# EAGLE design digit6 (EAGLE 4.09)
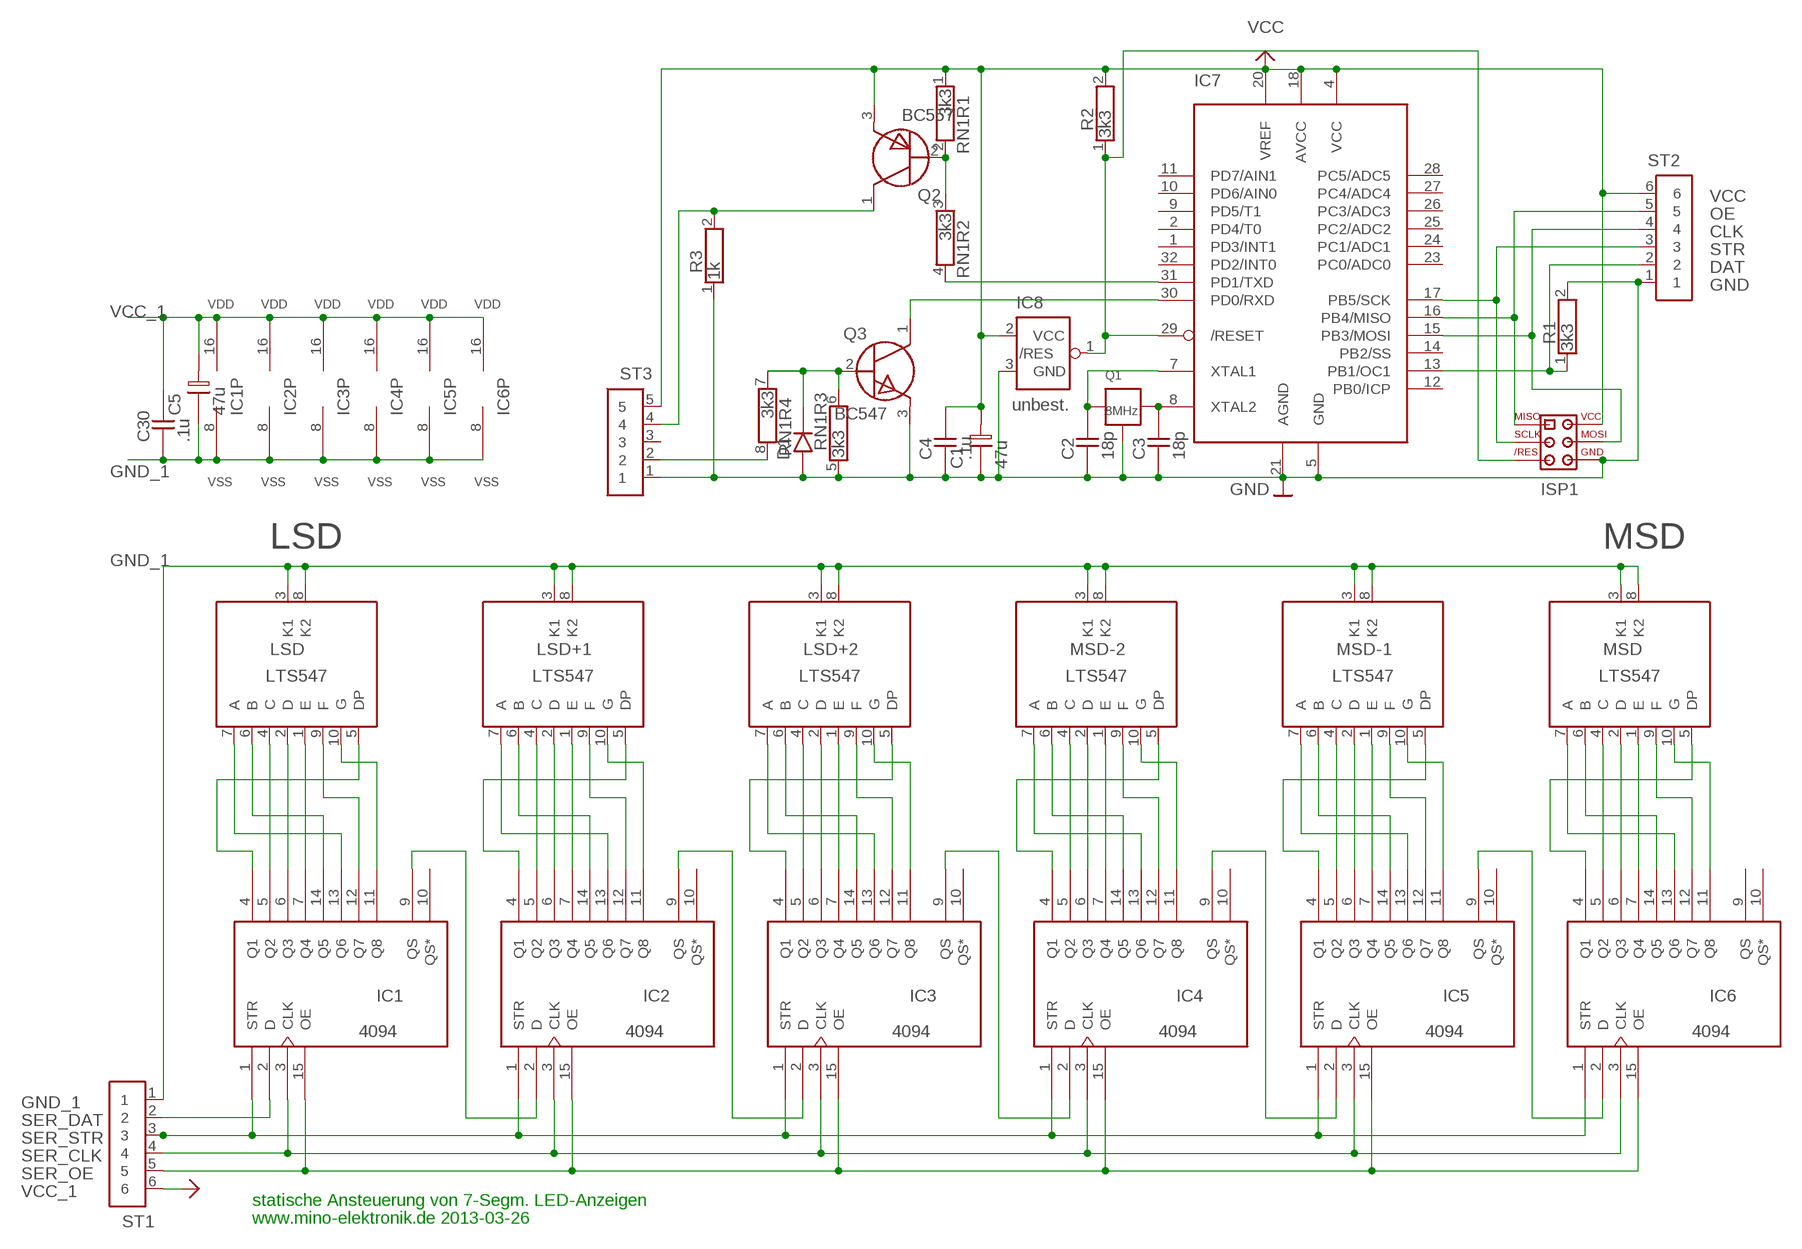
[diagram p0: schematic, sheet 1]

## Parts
C1  47u  ELK01  [02P100RA]
C2  18p  CAP01  [02P100QA]
C3  18p  CAP01  [02P100QA]
C4  .1u  CAP01  [02P100QA]
C5  47u  ELK01  [02P100RA]
C30  .1u  CAP01  [02P100QA]
D1  DIO03  [02P300IV]
IC1  4094  [SO-16]
IC2  4094  [SO-16]
IC3  4094  [SO-16]
IC4  4094  [SO-16]
IC5  4094  [SO-16]
IC6  4094  [SO-16]
IC7  90S4433F  [TQFP-32]
IC8  unbest.  MC34164  [TO92]
ISP1  AVR_ISP  [CON03X2]
LSD  LTS547  [SEGM13MM]
LSD+1  LTS547  [SEGM13MM]
LSD+2  LTS547  [SEGM13MM]
MSD  LTS547  [SEGM13MM]
MSD-1  LTS547  [SEGM13MM]
MSD-2  LTS547  [SEGM13MM]
Q1  8MHz  KERAM_RES  [KERAMRES]
Q2  BC557  BC327  [TO92]
Q3  BC547  BC337  [TO92]
R1  3k3  RES04  [02P400IL]
R2  3k3  RES04  [02P400IL]
R3  1k  RES04  [02P400IL]
RN1  3k3  R4P8  [08P100QA]
ST1  ST_6X1  [6X1]
ST2  ST_6X1  [6X1]
ST3  ST_5X1  [5X1]

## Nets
CLK: IC7.15(PB3/MOSI) ISP1.4 ST2.4
DAT: IC7.13(PB1/OC1) R1.1 ST2.2
GND: C1.N C2.1 C3.1 C4.1 D1.A IC7.5(GND) IC7.21(AGND) IC8.3(GND) ISP1.6 Q1.3 Q3.3(E) R1.2 R3.1 RN1.5 ST2.1 ST3.1
GND_1: C5.N C30.1 IC1.8(VSS) IC2.8(VSS) IC3.8(VSS) IC4.8(VSS) IC5.8(VSS) IC6.8(VSS) LSD+1.3(K1) LSD+1.8(K2) LSD+2.3(K1) LSD+2.8(K2) LSD.3(K1) LSD.8(K2) MSD-1.3(K1) MSD-1.8(K2) MSD-2.3(K1) MSD-2.8(K2) MSD.3(K1) MSD.8(K2) ST1.1
N$1: C3.2 IC7.8(XTAL2) Q1.2
N$2: C2.2 IC7.7(XTAL1) Q1.1
N$3: Q2.2(B) RN1.2 RN1.3
N$4: D1.K Q3.2(B) RN1.6 RN1.7
N$5: IC7.30(PD0/RXD) Q3.1(C)
N$6: IC7.29(/RESET) IC8.1(/RES) ISP1.5 R2.1
N$7: IC7.31(PD1/TXD) RN1.4
N$34: IC1.13(Q6) LSD.7(A)
N$35: IC1.14(Q5) LSD.6(B)
N$36: IC1.5(Q2) LSD.4(C)
N$37: IC1.6(Q3) LSD.2(D)
N$38: IC1.7(Q4) LSD.1(E)
N$39: IC1.12(Q7) LSD.9(F)
N$40: IC1.11(Q8) LSD.10(G)
N$41: IC1.4(Q1) LSD.5(DP)
N$42: IC2.13(Q6) LSD+1.7(A)
N$43: IC2.14(Q5) LSD+1.6(B)
N$44: IC2.5(Q2) LSD+1.4(C)
N$45: IC2.6(Q3) LSD+1.2(D)
N$46: IC2.7(Q4) LSD+1.1(E)
N$47: IC2.12(Q7) LSD+1.9(F)
N$48: IC2.11(Q8) LSD+1.10(G)
N$49: IC2.4(Q1) LSD+1.5(DP)
N$50: IC3.13(Q6) LSD+2.7(A)
N$51: IC3.14(Q5) LSD+2.6(B)
N$61: IC3.5(Q2) LSD+2.4(C)
N$63: IC3.6(Q3) LSD+2.2(D)
N$64: IC3.7(Q4) LSD+2.1(E)
N$65: IC3.12(Q7) LSD+2.9(F)
N$67: IC3.11(Q8) LSD+2.10(G)
N$68: IC3.4(Q1) LSD+2.5(DP)
N$69: IC4.13(Q6) MSD-2.7(A)
N$70: IC4.14(Q5) MSD-2.6(B)
N$71: IC4.5(Q2) MSD-2.4(C)
N$73: IC4.6(Q3) MSD-2.2(D)
N$74: IC4.7(Q4) MSD-2.1(E)
N$75: IC4.12(Q7) MSD-2.9(F)
N$76: IC4.11(Q8) MSD-2.10(G)
N$77: IC4.4(Q1) MSD-2.5(DP)
N$78: IC5.13(Q6) MSD-1.7(A)
N$79: IC5.14(Q5) MSD-1.6(B)
N$80: IC5.5(Q2) MSD-1.4(C)
N$81: IC5.6(Q3) MSD-1.2(D)
N$82: IC5.7(Q4) MSD-1.1(E)
N$83: IC5.12(Q7) MSD-1.9(F)
N$84: IC5.11(Q8) MSD-1.10(G)
N$85: IC5.4(Q1) MSD-1.5(DP)
N$87: IC6.13(Q6) MSD.7(A)
N$89: IC6.14(Q5) MSD.6(B)
N$90: IC6.5(Q2) MSD.4(C)
N$91: IC6.6(Q3) MSD.2(D)
N$92: IC6.7(Q4) MSD.1(E)
N$93: IC6.12(Q7) MSD.9(F)
N$94: IC6.11(Q8) MSD.10(G)
N$95: IC6.4(Q1) MSD.5(DP)
N$102: IC1.9(QS) IC2.2(D)
N$103: IC2.9(QS) IC3.2(D)
N$104: IC3.9(QS) IC4.2(D)
N$105: IC4.9(QS) IC5.2(D)
N$106: IC5.9(QS) IC6.2(D)
OE: IC7.16(PB4/MISO) ISP1.1 ST2.5
RXD: RN1.8 ST3.2
SER_CLK: IC1.3(CLK) IC2.3(CLK) IC3.3(CLK) IC4.3(CLK) IC5.3(CLK) IC6.3(CLK) ST1.4
SER_DAT: IC1.2(D) ST1.2
SER_OE: IC1.15(OE) IC2.15(OE) IC3.15(OE) IC4.15(OE) IC5.15(OE) IC6.15(OE) ST1.5
SER_STR: IC1.1(STR) IC2.1(STR) IC3.1(STR) IC4.1(STR) IC5.1(STR) IC6.1(STR) ST1.3
STR: IC7.17(PB5/SCK) ISP1.3 ST2.3
TXD: Q2.1(C) R3.2 ST3.4
VCC: C1.P C4.2 IC7.4(VCC) IC7.18(AVCC) IC7.20(VREF) IC8.2(VCC) ISP1.2 Q2.3(E) R2.2 RN1.1 ST2.6 ST3.5
VCC_1: C5.P C30.2 IC1.16(VDD) IC2.16(VDD) IC3.16(VDD) IC4.16(VDD) IC5.16(VDD) IC6.16(VDD) ST1.6
Unconnected: IC1.10(QS*) IC2.10(QS*) IC3.10(QS*) IC4.10(QS*) IC5.10(QS*) IC6.9(QS) IC6.10(QS*) IC7.1(PD3/INT1) IC7.2(PD4/T0) IC7.9(PD5/T1) IC7.10(PD6/AIN0) IC7.11(PD7/AIN1) IC7.12(PB0/ICP) IC7.14(PB2/SS) IC7.23(PC0/ADC0) IC7.24(PC1/ADC1) IC7.25(PC2/ADC2) IC7.26(PC3/ADC3) IC7.27(PC4/ADC4) IC7.28(PC5/ADC5) IC7.32(PD2/INT0) ST3.3

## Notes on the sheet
- LSD | MSD
- statische Ansteuerung von 7-Segm. LED-Anzeigen
- www.mino-elektronik.de 2013-03-26

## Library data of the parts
C1 C5 = DISCRETE:ELK01
C2-C4 C30 = DISCRETE:CAP01
D1 = DISCRETE:DIO03
IC1-IC6 = SMD_40XX:4094
IC7 = MINO:90S4433F
IC8 = MINO:MC34164
ISP1 = CONNEC:AVR_ISP
LSD LSD+1 LSD+2 MSD MSD-1 MSD-2 = MINO:LTS547
Q1 = MINO:KERAM_RES
Q2 = ANALOG:BC327
Q3 = ANALOG:BC337
R1-R3 = DISCRETE:RES04
RN1 = DISCRETE:R4P8
ST1 ST2 = CONNEC:ST_6X1
ST3 = CONNEC:ST_5X1

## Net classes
0 default: width 0.203 mm, clearance 0.406 mm

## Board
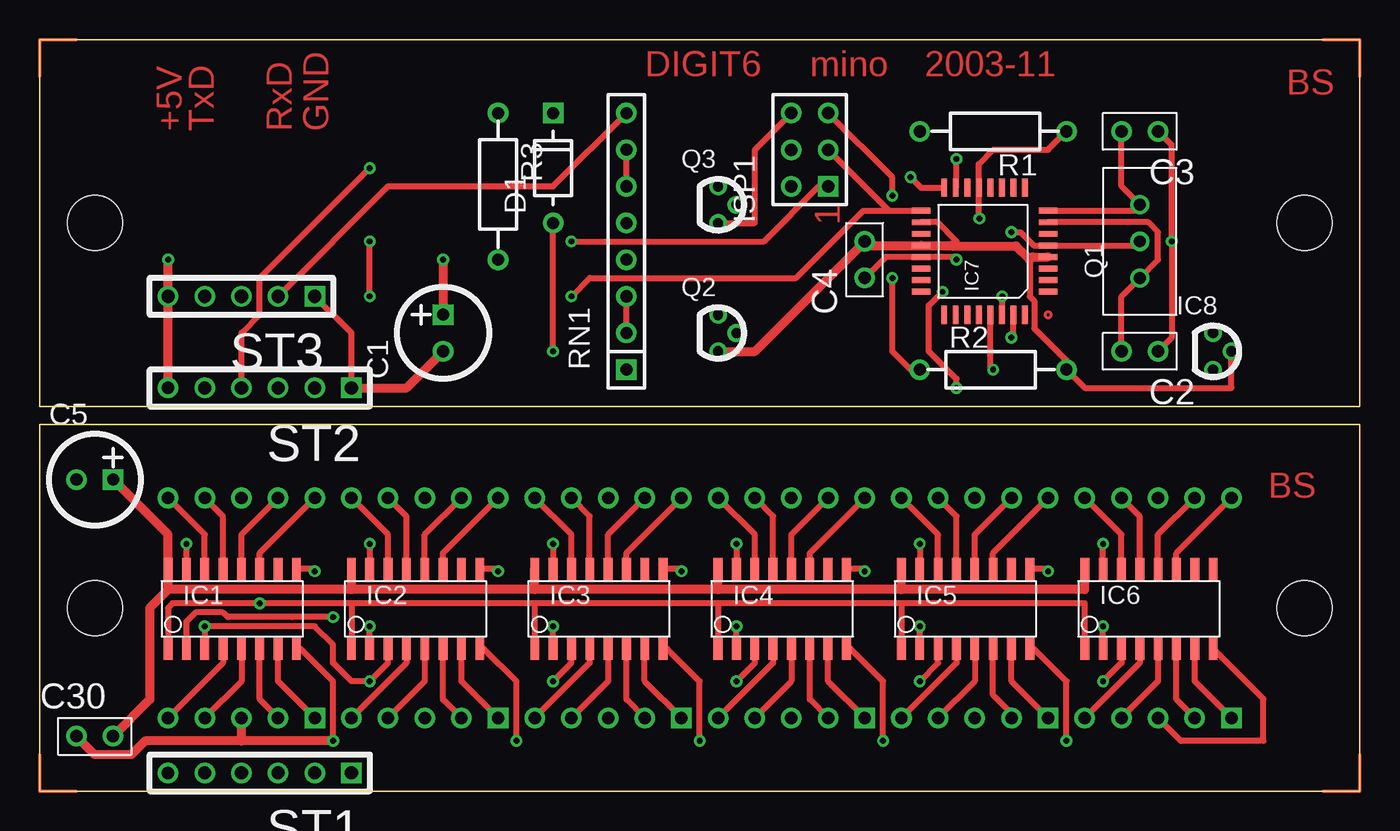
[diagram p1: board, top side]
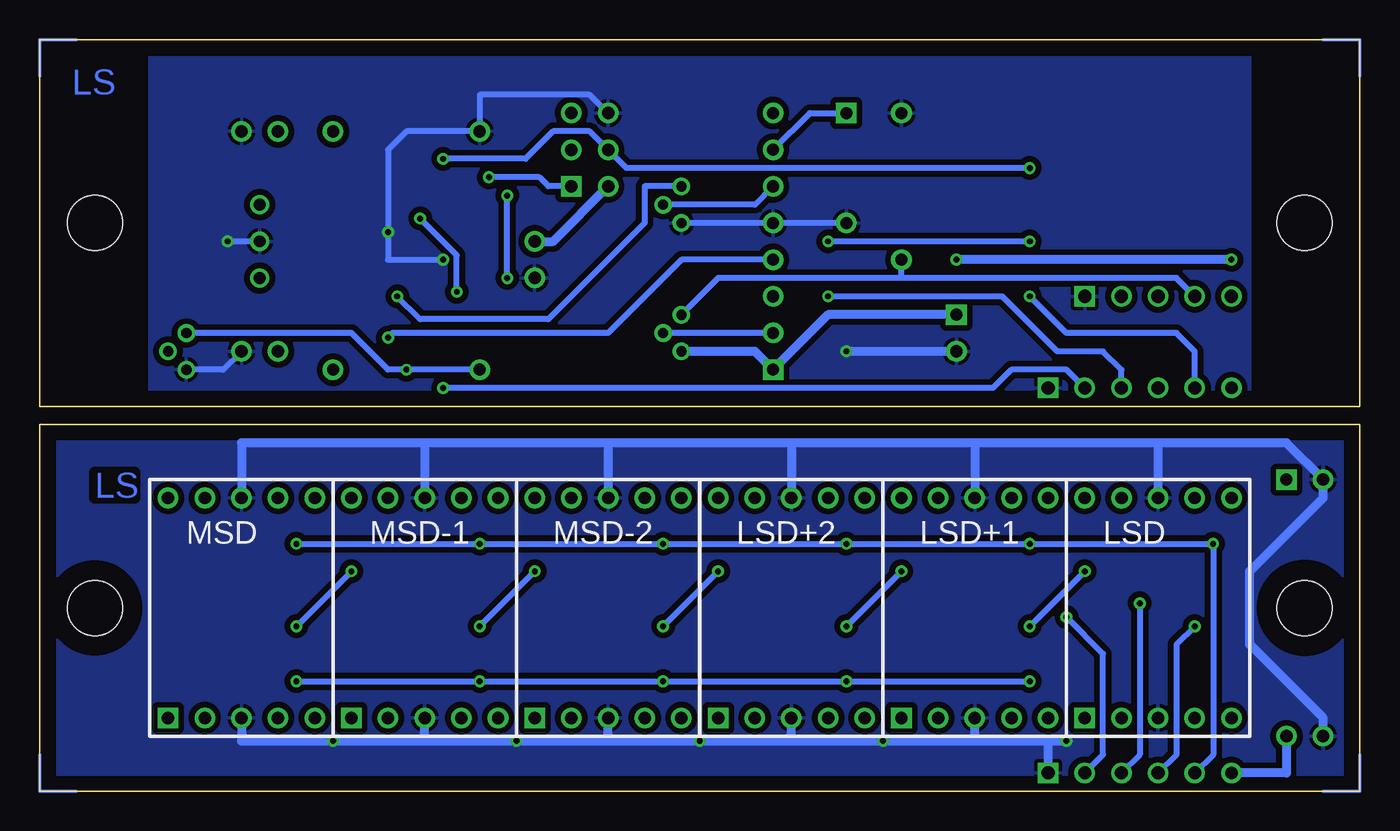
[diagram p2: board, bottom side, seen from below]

Size 91.44 x 52.07 mm. Coordinates in mm from the lower left corner, seen from the top.
Outline: 91.44,0 0,0 0,25.4 91.44,25.4 91.44,0
Outline: 0,26.67 91.44,26.67 91.44,52.07 0,52.07 0,26.67
Copper layers used: Top, Bottom
Holes 3.81 mm at 87.63,12.7 3.81,12.7 87.63,39.37 3.81,39.37
bRestrict: area 84.5,9.5 to 90.8,15.9; area 0.6,9.5 to 7,15.9

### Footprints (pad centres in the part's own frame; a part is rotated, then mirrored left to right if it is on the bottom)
02P100RA = drill 0.838 pad 1.422 round: N 0,0 | drill 0.838 pad 1.422 square: P 2.54,0
02P100QA = drill 0.864 pad 1.422 round: 1 0,0; 2 2.54,0
02P300IV = drill 0.838 pad 1.422 round: A 0,0 | drill 0.838 pad 1.422 square: K 7.62,0
SO-16 = smd 0.61 x 1.524: 1 -3.81,-2.819; 2 -2.54,-2.819; 3 -1.27,-2.819; 4 0,-2.819; 5 1.27,-2.819; 6 2.54,-2.819; 7 3.81,-2.819; 8 5.08,-2.819; 9 5.08,2.692; 10 3.81,2.692; 11 2.54,2.692; 12 1.27,2.692; 13 0,2.692; 14 -1.27,2.692; 15 -2.54,2.692; 16 -3.81,2.692
TQFP-32 = smd 0.406 x 1.27: 1 1.6,0; 2 2.4,0; 3 3.2,0; 4 4,0; 5 4.8,0; 6 5.6,0; 7 6.4,0; 8 7.2,0; 17 7.2,8.8; 18 6.4,8.8; 19 5.6,8.8; 20 4.8,8.8; 21 4,8.8; 22 3.2,8.8; 23 2.4,8.8; 24 1.6,8.8 | smd 1.27 x 0.406: 9 8.8,1.6; 10 8.8,2.4; 11 8.8,3.2; 12 8.8,4; 13 8.8,4.8; 14 8.8,5.6; 15 8.8,6.4; 16 8.8,7.2; 25 0,7.2; 26 0,6.4; 27 0,5.6; 28 0,4.8; 29 0,4; 30 0,3.2; 31 0,2.4; 32 0,1.6
TO92 = drill 0.711 pad 1.118 round: 1 0,2.54; 2 1.27,1.27; 3 0,0
CON03X2 = drill 0.864 pad 1.422 square: 1 0,0 | drill 0.864 pad 1.422 round: 2 0,2.54; 3 2.54,0; 4 2.54,2.54; 5 5.08,0; 6 5.08,2.54
SEGM13MM = drill 0.864 pad 1.422 square: 1 0,0 | drill 0.864 pad 1.422 round: 2 2.54,0; 3 5.08,0; 4 7.62,0; 5 10.16,0; 6 10.16,15.24; 7 7.62,15.24; 8 5.08,15.24; 9 2.54,15.24; 10 0,15.24
KERAMRES = drill 0.813 round: 1 -2.54,0; 2 2.54,0; 3 0,0
02P400IL = drill 0.838 pad 1.422 round: 1 0,0; 2 10.16,0
08P100QA = drill 0.838 pad 1.422 square: 1 0,0 | drill 0.838 pad 1.422 round: 2 2.54,0; 3 5.08,0; 4 7.62,0; 5 10.16,0; 6 12.7,0; 7 15.24,0; 8 17.78,0
6X1 = drill 0.914 pad 1.422 square: 1 1.27,1.27 | drill 0.914 pad 1.422 round: 2 3.81,1.27; 3 6.35,1.27; 4 8.89,1.27; 5 11.43,1.27 | drill 0.864 pad 1.422 round: 6 13.97,1.27
5X1 = drill 0.914 pad 1.422 square: 1 0,0 | drill 0.914 pad 1.422 round: 2 2.54,0; 3 5.08,0; 4 7.62,0; 5 10.16,0

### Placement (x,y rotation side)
C1  27.94,30.48 90 top
C2  77.47,30.48 180 top
C3  77.47,45.72 180 top
C4  57.15,35.56 90 top
C5  2.54,21.59 0 top
C30  2.54,3.81 0 top
D1  35.56,39.37 90 top
IC1  12.7,12.7 0 top
IC2  25.4,12.7 0 top
IC3  38.1,12.7 0 top
IC4  50.8,12.7 0 top
IC5  63.5,12.7 0 top
IC6  76.2,12.7 0 top
IC7  69.85,33.02 90 top
IC8  81.28,29.21 0 top
ISP1  54.61,41.91 90 top
LSD  19.05,5.08 0 bottom
LSD+1  31.75,5.08 0 bottom
LSD+2  44.45,5.08 0 bottom
MSD  82.55,5.08 0 bottom
MSD-1  69.85,5.08 0 bottom
MSD-2  57.15,5.08 0 bottom
Q1  76.2,38.1 90 top
Q2  46.99,30.48 0 top
Q3  46.99,39.37 0 top
R1  71.12,45.72 180 top
R2  60.96,29.21 0 top
R3  31.75,46.99 270 top
RN1  40.64,29.21 90 top
ST1  22.86,2.54 180 top
ST2  22.86,29.21 180 top
ST3  19.05,34.29 180 top

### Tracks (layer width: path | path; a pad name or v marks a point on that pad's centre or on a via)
CLK  (via drill 0.41)
  Top 0.406: IC7.15 63.45,43.77 v63.5,43.81 | v22.86,43.18 15.24,35.56 15.24,33.02 13.97,31.75 ST2.4
  Bottom 0.406: v63.5,43.81 57.78,43.81 55.88,45.72 53.34,45.72 ISP1.4 50.8,43.18 v22.86,43.18
DAT  (via drill 0.41)
  Top 0.406: R1.1 69.85,44.45 66.04,44.45 65.05,43.46 IC7.13 65.05,39.73 v65.09,39.69 | v62.55,34.61 61.59,33.66 61.59,30.48 63.5,28.57 v63.5,27.94
  Bottom 0.406: v65.09,39.69 62.55,37.15 v62.55,34.61 | v63.5,27.94 25.4,27.94 24.13,29.21 20.32,29.21 ST2.2
GND  (via drill 0.41)
  Top 0.406: ST2.1 21.59,31.75 ST3.1 | v35.56,30.48 D1.A | C4.1 58.61,37.02 IC7.21 63.31,37.02 v63.5,36.83 | v67.31,38.73 67.94,38.73 68.86,37.82 IC7.5 75.92,37.82 Q1.3 | C3.1 78.42,44.77 v78.42,38.1 78.42,31.43 C2.1 | ISP1.6 49.53,44.45 49.53,39.37 Q3.3
  Top 0.61: ST2.1 25.4,27.94 C1.N
  Bottom 0.406: D1.A RN1.5 Q3.3 | v63.5,36.83 67.31,36.83 v67.31,38.73 67.31,44.45 66.04,45.72 R1.2 60.96,48.26 53.34,48.26 ISP1.6 | Q1.3 v78.42,38.1 | IC8.3 78.74,29.21 C2.1
  Bottom 0.61: C1.N v35.56,30.48
  pour Bottom: 7.62,51.44 7.62,27.3 83.82,27.62 83.82,51.44
GND_1  (via drill 0.41)
  Top 0.406: IC6.8 84.77,6.39 84.77,3.49 79.06,3.49 MSD.3 | IC5.8 68.86,9.88 71.12,7.62 v71.12,3.49 | IC4.8 56.16,9.88 58.42,7.62 v58.42,3.49 | IC3.8 43.46,9.88 45.72,7.62 v45.72,3.49 | IC2.8 30.76,9.88 33.02,7.62 v33.02,3.49 | IC1.8 18.06,9.88 20.32,7.62 v20.32,3.49
  Top 0.61: 13.97,3.49 LSD.3 | v20.32,3.49 13.97,3.49 | 13.97,3.49 7.3,3.49 6.35,2.54 3.81,2.54 C30.1
  Bottom 0.61: 26.67,3.49 v20.32,3.49 | 26.67,3.49 LSD+1.3 | 21.59,3.49 ST1.1 | 39.37,3.49 v33.02,3.49 26.67,3.49 | 52.07,3.49 v45.72,3.49 39.37,3.49 | 64.77,3.49 v58.42,3.49 52.07,3.49 | 64.77,3.49 v71.12,3.49 77.47,3.49 MSD.3 | 64.77,3.49 MSD-1.3 | 52.07,3.49 MSD-2.3 | 39.37,3.49 LSD+2.3 | C30.1 2.54,5.08 7.62,10.16 7.62,15.24 2.54,20.32 C5.N 5.08,24.13 13.97,24.13 | 13.97,24.13 LSD.8 | 13.97,24.13 26.67,24.13 | 26.67,24.13 39.37,24.13 | 39.37,24.13 52.07,24.13 | 52.07,24.13 64.77,24.13 | 64.77,24.13 77.47,24.13 MSD.8 | 64.77,24.13 MSD-1.8 | 52.07,24.13 MSD-2.8 | 39.37,24.13 LSD+2.8 | 26.67,24.13 LSD+1.8
  pour Bottom: 90.81,24.77 90.81,0.64 0.64,0.64 0.64,24.77
N$1
  Top 0.406: IC7.8 75.78,40.22 Q1.2 74.93,41.91 C3.2
N$2
  Top 0.406: IC7.7 76.78,39.42 77.47,38.73 77.47,36.83 Q1.1 74.93,34.29 C2.2
N$3
  Top 0.406: RN1.2 RN1.3
  Bottom 0.406: RN1.2 Q2.2
N$4
  Top 0.406: RN1.6 RN1.7
  Bottom 0.406: D1.K 38.1,46.99 RN1.7 | Q3.2 41.91,40.64 RN1.6
N$5  (via drill 0.41)
  Top 0.406: IC7.30 66.65,34.27 v66.67,34.29
  Bottom 0.406: v66.67,34.29 65.09,32.7 56.2,32.7 49.53,39.37 49.53,41.91 Q3.1
N$6  (via drill 0.41)
  Top 0.406: IC7.29 65.85,29.4 v66.04,29.21 | R2.1 60.33,29.21 59.05,30.48 v59.05,35.56 | v59.05,41.27 59.05,42.55 ISP1.5
  Bottom 0.406: IC8.1 69.85,31.75 67.31,29.21 v66.04,29.21 R2.1 | v59.05,35.56 v59.05,41.27
N$7  (via drill 0.41)
  Top 0.406: IC7.31 67.45,31.57 v67.31,31.43
  Bottom 0.406: RN1.4 46.99,36.83 52.07,31.75 66.99,31.75 v67.31,31.43
N$8
  Bottom 0.254: 88.9,52.07 91.44,52.07 91.44,49.53
N$9
  Top 0.254: 88.9,52.07 91.44,52.07 91.44,49.53
N$10
  Bottom 0.254: 2.54,0 0,0 0,2.54
N$13
  Top 0.254: 2.54,0 0,0 0,2.54
N$14
  Top 0.254: 91.44,2.54 91.44,0 88.9,0
N$15
  Bottom 0.254: 88.9,0 91.44,0 91.44,2.54
N$16
  Top 0.254: 2.54,52.07 0,52.07 0,49.53
N$17
  Bottom 0.254: 2.54,52.07 0,52.07 0,49.53
N$34
  Top 0.406: IC1.13 12.7,19.05 LSD.7
N$35
  Top 0.406: IC1.14 11.43,17.78 LSD.6
N$36
  Top 0.406: IC1.5 13.97,7.62 LSD.4
N$37
  Top 0.406: IC1.6 15.24,6.35 LSD.2
N$38
  Top 0.406: IC1.7 16.51,7.62 LSD.1
N$39
  Top 0.406: IC1.12 13.97,17.78 LSD.9
N$40
  Top 0.406: IC1.11 15.24,16.51 LSD.10
N$41
  Top 0.406: IC1.4 12.7,8.89 LSD.5
N$42
  Top 0.406: IC2.13 25.4,19.05 LSD+1.7
N$43
  Top 0.406: IC2.14 24.13,17.78 LSD+1.6
N$44
  Top 0.406: IC2.5 26.67,7.62 LSD+1.4
N$45
  Top 0.406: IC2.6 27.94,6.35 LSD+1.2
N$46
  Top 0.406: IC2.7 29.21,7.62 LSD+1.1
N$47
  Top 0.406: IC2.12 26.67,17.78 LSD+1.9
N$48
  Top 0.406: IC2.11 27.94,16.51 LSD+1.10
N$49
  Top 0.406: LSD+1.5 25.4,8.89 IC2.4
N$50
  Top 0.406: IC3.13 38.1,19.05 LSD+2.7
N$51
  Top 0.406: IC3.14 36.83,17.78 LSD+2.6
N$61
  Top 0.406: IC3.5 39.37,7.62 LSD+2.4
N$63
  Top 0.406: IC3.6 40.64,6.35 LSD+2.2
N$64
  Top 0.406: IC3.7 41.91,7.62 LSD+2.1
N$65
  Top 0.406: IC3.12 39.37,17.78 LSD+2.9
N$67
  Top 0.406: IC3.11 40.64,16.51 LSD+2.10
N$68
  Top 0.406: IC3.4 38.1,8.89 LSD+2.5
N$69
  Top 0.406: IC4.13 50.8,19.05 MSD-2.7
N$70
  Top 0.406: IC4.14 49.53,17.78 MSD-2.6
N$71
  Top 0.406: IC4.5 52.07,7.62 MSD-2.4
N$73
  Top 0.406: IC4.6 53.34,6.35 MSD-2.2
N$74
  Top 0.406: IC4.7 54.61,7.62 MSD-2.1
N$75
  Top 0.406: IC4.12 52.07,17.78 MSD-2.9
N$76
  Top 0.406: IC4.11 53.34,16.51 MSD-2.10
N$77
  Top 0.406: IC4.4 50.8,8.89 MSD-2.5
N$78
  Top 0.406: IC5.13 63.5,19.05 MSD-1.7
N$79
  Top 0.406: IC5.14 62.23,17.78 MSD-1.6
N$80
  Top 0.406: IC5.5 64.77,7.62 MSD-1.4
N$81
  Top 0.406: MSD-1.2 67.31,5.4 66.04,6.67 IC5.6
N$82
  Top 0.406: IC5.7 67.31,7.62 MSD-1.1
N$83
  Top 0.406: IC5.12 64.77,17.78 MSD-1.9
N$84
  Top 0.406: IC5.11 66.04,16.51 MSD-1.10
N$85
  Top 0.406: IC5.4 63.5,8.89 MSD-1.5
N$87
  Top 0.406: IC6.13 76.2,19.05 MSD.7
N$89
  Top 0.406: IC6.14 74.93,17.78 MSD.6
N$90
  Top 0.406: IC6.5 77.47,7.62 MSD.4
N$91
  Top 0.406: IC6.6 78.74,6.35 MSD.2
N$92
  Top 0.406: IC6.7 80.01,7.62 MSD.1
N$93
  Top 0.406: IC6.12 77.47,17.78 MSD.9
N$94
  Top 0.406: IC6.11 78.74,16.51 MSD.10
N$95
  Top 0.406: IC6.4 76.2,8.89 MSD.5
N$102  (via drill 0.41)
  Top 0.406: IC1.9 18.9,15.39 v19.05,15.24 | 22.86,9.84 IC2.2 v22.86,11.43
  Bottom 0.406: v22.86,11.43 v19.05,15.24
N$103  (via drill 0.41)
  Top 0.406: IC2.9 31.6,15.39 v31.75,15.24 | 35.56,9.84 IC3.2 v35.56,11.43
  Bottom 0.406: v35.56,11.43 v31.75,15.24
N$104  (via drill 0.41)
  Top 0.406: IC3.9 44.3,15.39 v44.45,15.24 | 48.26,9.84 IC4.2 v48.26,11.43
  Bottom 0.406: v48.26,11.43 v44.45,15.24
N$105  (via drill 0.41)
  Top 0.406: IC4.9 57,15.39 v57.15,15.24 | 60.96,9.84 IC5.2 v60.96,11.43
  Bottom 0.406: v60.96,11.43 v57.15,15.24
N$106  (via drill 0.41)
  Top 0.406: IC5.9 69.7,15.39 v69.85,15.24 | 73.66,9.84 IC6.2 v73.66,11.43
  Bottom 0.406: v73.66,11.43 v69.85,15.24
OE  (via drill 0.41)
  Top 0.406: IC7.16 61.05,41.82 v60.33,42.55 | ISP1.1 53.98,41.91 50.16,38.1 v36.83,38.1 | v22.86,34.29 v22.86,38.1
  Bottom 0.406: ISP1.1 56.2,41.91 56.83,42.55 v60.33,42.55 | ST2.5 11.43,30.48 12.7,31.75 20.32,31.75 v22.86,34.29 | v22.86,38.1 v36.83,38.1
RXD
  Top 0.406: ST3.2 24.13,41.91 35.56,41.91 RN1.8
SER_CLK  (via drill 0.41)
  Top 0.406: 11.43,9.84 IC1.3 v11.43,11.43 19.05,11.43 20.32,10.16 20.32,8.89 21.59,7.62 v22.86,7.62 24.13,8.89 IC2.3 | IC3.3 36.83,8.89 v35.56,7.62 | IC4.3 49.53,8.89 v48.26,7.62 | IC5.3 62.23,8.89 v60.96,7.62 | IC6.3 74.93,8.89 v73.66,7.62
  Bottom 0.406: ST1.4 12.7,2.54 12.7,10.16 v11.43,11.43 | v22.86,7.62 v35.56,7.62 v48.26,7.62 v60.96,7.62 v73.66,7.62
SER_DAT  (via drill 0.41)
  Top 0.406: v20.32,12.06 17.46,12.06 13.02,12.06 12.7,12.38 10.79,12.38 10.16,11.75 IC1.2
  Bottom 0.406: ST1.2 17.78,2.54 17.78,9.53 v20.32,12.06
SER_OE  (via drill 0.41)
  Top 0.406: v10.16,17.14 IC1.15 | IC6.15 v73.66,17.14 | v60.96,17.14 IC5.15 | v48.26,17.14 IC4.15 | v35.56,17.14 IC3.15 | v22.86,17.14 IC2.15
  Bottom 0.406: v73.66,17.14 v60.96,17.14 v48.26,17.14 v35.56,17.14 v22.86,17.14 v10.16,17.14 10.16,2.54 ST1.5
SER_STR  (via drill 0.41)
  Top 0.406: IC1.1 8.89,12.7 9.21,13.02 v15.24,13.02 21.59,13.02 | 21.59,9.84 IC2.1 21.59,13.02 | 59.69,13.02 72.39,13.02 IC6.1 72.39,9.84 | 59.69,13.02 46.99,13.02 | 46.99,13.02 34.29,13.02 | 34.29,13.02 21.59,13.02 | 59.69,13.02 IC5.1 | 46.99,13.02 IC4.1 | 34.29,13.02 IC3.1
  Bottom 0.406: ST1.3 15.24,2.54 v15.24,13.02
STR  (via drill 0.41)
  Top 0.406: 58.84,40.22 IC7.17 | 58.84,40.22 ISP1.3 | 58.84,40.22 57.05,40.22 52.39,35.56 38.1,35.56 v36.83,34.29
  Bottom 0.406: ST2.3 16.51,29.21 17.78,30.48 20.95,30.48 24.77,34.29 v36.83,34.29
TXD
  Bottom 0.406: ST3.4 12.7,35.56 31.75,35.56 | 31.75,35.56 44.45,35.56 Q2.1 | 31.75,35.56 R3.2
VCC  (via drill 0.41)
  Top 0.406: C4.2 57.43,37.82 | IC7.18 62.18,39.42 63.5,38.1 63.22,37.82 IC7.20 | 63.15,37.82 63.18,37.78 | 68.58,36.83 68.58,34.29 68.9,33.97 68.9,32.07 71.12,29.84 R2.2 72.39,27.94 82.55,27.94 IC8.2
  Top 0.61: ST2.6 ST3.5 v8.89,36.83 | v27.94,36.83 C1.P | 57.43,37.82 IC7.20 63.15,37.82 | 63.18,37.78 67.63,37.78 68.58,36.83 68.77,37.02 IC7.4 | Q2.3 49.53,30.48 C4.2
  Bottom 0.61: Q2.3 41.91,30.48 RN1.1 36.83,33.02 C1.P | v8.89,36.83 v27.94,36.83 | C4.2 55.88,38.1 ISP1.2
VCC_1
  Top 0.406: 8.89,15.24 IC1.16
  Top 0.61: IC6.16 72.39,13.97 59.69,13.97 | 59.69,13.97 IC5.16 | 59.69,13.97 46.99,13.97 | 46.99,13.97 34.29,13.97 | 34.29,13.97 21.59,13.97 | 21.59,13.97 8.89,13.97 | 8.89,13.97 8.89,15.24 | 46.99,13.97 IC4.16 | 34.29,13.97 IC3.16 | 21.59,13.97 IC2.16 | IC1.16 8.89,17.78 C5.P | 8.89,13.97 7.62,12.7 7.62,6.35 C30.2
  Bottom 0.61: ST1.6 5.08,1.27 C30.2

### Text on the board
Top: DIGIT6 | mino | 2003-11 | BS | +5V | TxD | RxD | GND | 1 | BS
Bottom: LS | LS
